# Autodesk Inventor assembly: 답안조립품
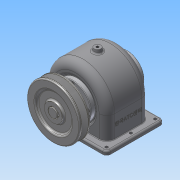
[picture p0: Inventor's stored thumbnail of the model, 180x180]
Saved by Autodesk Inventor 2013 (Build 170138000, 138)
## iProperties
Created: 2015-09
Part Number: 답안조립품
Document SubType Name: Assembly
Designer: ST
Author: ST
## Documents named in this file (13)
- C:\Users\ST\Desktop\450907V1019\답안조립품.iam
- C:\Users\ST\Desktop\450907V1019\1-본체.ipt
- C:\Users\ST\Desktop\450907V1019\뒤커버.ipt
- C:\Users\ST\Desktop\450907V1019\앞커버.ipt
- C:\Users\ST\Desktop\450907V1019\오일 실 17 32 8.ipt
- C:\Users\ST\Desktop\450907V1019\베어링 6203.ipt
- C:\Users\ST\Desktop\450907V1019\축.ipt
- C:\Users\ST\Desktop\450907V1019\키 - 5 x 5 x 18.ipt
- C:\Users\ST\Desktop\450907V1019\키 - 6 x 6 x 22.ipt
- C:\Users\ST\Desktop\450907V1019\V-벨트풀리.ipt
- C:\Users\ST\Desktop\450907V1019\볼트 M3 x 8.ipt
- C:\Users\ST\Desktop\450907V1019\볼트 M3 x 10.ipt
- C:\Users\ST\Desktop\450907V1019\멈춤나사 - M4x10.ipt
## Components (10 placed, 4 different names)
1. 1-본체:1
2. V-벨트풀리:1 — 각도:1
3. ISO 4762 M3 x 8:1
4. ISO 4762 M3 x 8:2
5. ISO 4762 M3 x 8:3
6. ISO 4762 M3 x 8:4
7. ISO 4762 M3 x 10:1
8. ISO 4762 M3 x 10:2
9. ISO 4762 M3 x 10:3
10. ISO 4762 M3 x 10:4
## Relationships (1: Angle 1)
- 각도:1 [Angle]: V-벨트풀리:1
